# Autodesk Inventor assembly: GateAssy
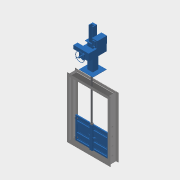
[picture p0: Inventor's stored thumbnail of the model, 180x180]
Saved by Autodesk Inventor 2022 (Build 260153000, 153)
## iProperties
RuleStatus: InUse
description: 0:0:
manufacturer: 0:0:ADJ
model: 0:0:Gate
url: 0:0:
Created: 2018-04
Part Number: GateAssy
Material: 一般
Document SubType Name: Assembly
Designer: ADJ
Mass: 540585 g
Surface Area: 155674 cm^2
Volume: 189799 cm^3
Density: 2.8482 g/cm^3
Catalog Web Link: www.autodesk.co.jp/
Vendor: ADJ
_SolveAssemblyDoc: Frame Generator Solve Assembly
_Version: 25.0.0
ゲートフレーム高さ: 2000.00 mm
水門高さ: 800.00 mm
水門幅: 1200.00 mm
重量: 540.91Kg
材質: 鉄
製造年月日: 2018/06/11
Author: ADJ
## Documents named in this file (11)
- C:\Users\shimo\Desktop\Inventor2022_Data\Workspaces\作業スペース\GateAssy.iam
- C:\Users\shimo\Desktop\Inventor2022_Data\Workspaces\作業スペース\gate_skelton.ipt
- C:\Users\shimo\Desktop\Inventor2022_Data\Workspaces\作業スペース\GateAssy\Frame\Frame0001.iam
- C:\Users\shimo\Desktop\Inventor2022_Data\Workspaces\作業スペース\Spindle.ipt
- C:\Users\shimo\Desktop\Inventor2022_Data\Workspaces\作業スペース\Handle.ipt
- C:\Users\shimo\Desktop\Inventor2022_Data\Workspaces\作業スペース\Mech.ipt
- C:\Users\shimo\Desktop\Inventor2022_Data\Workspaces\作業スペース\gate_3D.ipt
- C:\Users\shimo\Desktop\Inventor2022_Data\Workspaces\作業スペース\GateAssy\デザイン アクセラレータ\ボルト締結1.iam
- C:\Users\shimo\Desktop\Inventor2022_Data\Workspaces\作業スペース\GateAssy\デザイン アクセラレータ\ボルト締結2.iam
- C:\Users\shimo\Desktop\Inventor2022_Data\Libraries\Content Center Files\ja-JP\JIS B 1181(3)\JIS B 1181 - M30x2.ipt
- C:\Users\shimo\Desktop\Inventor2022_Data\Workspaces\作業スペース\Roller.ipt
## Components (16 placed, 9 different names)
1. gate_skelton:1 — フラッシュ:3, メイト:2, フラッシュ:4
2. Frame0001:1 [sub-assembly] — メイト:29, メイト:30, メイト:31, メイト:32
3. Spindle:1 — メイト:3, メイト:4, 角度:1
4. Handle:1 — 回転:1
5. Mech:1 — 回転:1, フラッシュ:3, メイト:2, フラッシュ:4
6. gate_3D:1 — フラッシュ:5, フラッシュ:6, フラッシュ:7, メイト:3, メイト:4, 角度:1, 挿入:5, 挿入:6, 挿入:7, 挿入:8
7. ボルト締結:1 [sub-assembly] — メイト:29, メイト:30
8. ボルト締結:2 [sub-assembly] — メイト:31, メイト:32
9. JIS B 1181 M30x2:1
10. JIS B 1181 M30x2:2
11. JIS B 1181 M30x2:3
12. JIS B 1181 M30x2:4
13. Roller:1 — 挿入:5
14. Roller:2 — 挿入:6
15. Roller:3 — 挿入:7
16. Roller:4 — 挿入:8
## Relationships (18: Mate 7, Flush 5, Insert 4, RevoluteJoint 1, Angle 1)
- 回転:1 [RevoluteJoint]: Handle:1 ↔ Mech:1
- フラッシュ:3 [Flush]: gate_skelton:1 ↔ Mech:1
- メイト:2 [Mate]: gate_skelton:1 ↔ Mech:1
- フラッシュ:4 [Flush]: gate_skelton:1 ↔ Mech:1
- フラッシュ:5 [Flush]: gate_3D:1
- フラッシュ:6 [Flush]: gate_3D:1
- フラッシュ:7 [Flush]: gate_3D:1
- メイト:3 [Mate]: Spindle:1 ↔ gate_3D:1
- メイト:4 [Mate]: Spindle:1 ↔ gate_3D:1
- 角度:1 [Angle]: Spindle:1 ↔ gate_3D:1
- メイト:29 [Mate]: Frame0001:1 ↔ ボルト締結:1
- メイト:30 [Mate]: Frame0001:1 ↔ ボルト締結:1
- メイト:31 [Mate]: Frame0001:1 ↔ ボルト締結:2
- メイト:32 [Mate]: Frame0001:1 ↔ ボルト締結:2
- 挿入:5 [Insert]: gate_3D:1 ↔ Roller:1
- 挿入:6 [Insert]: gate_3D:1 ↔ Roller:2
- 挿入:7 [Insert]: gate_3D:1 ↔ Roller:3
- 挿入:8 [Insert]: gate_3D:1 ↔ Roller:4
